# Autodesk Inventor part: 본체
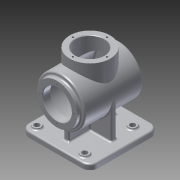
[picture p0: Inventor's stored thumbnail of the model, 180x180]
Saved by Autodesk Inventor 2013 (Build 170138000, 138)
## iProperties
Created: 2015-07
Part Number: 본체
Material: 알루미늄 6061
Document SubType Name: Modeling
Designer: Administrator
Density: 2.71 g/cm^3
Mass: 1276.78 g
Surface Area: 1269.7 cm^2
Volume: 471.138 cm^3
Author: Administrator
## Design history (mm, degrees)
sketch "스케치1"
  geometry: L1 (65, -65)-(-65, -65); L2 (-65, -65)-(-65, 65); L3 (-65, 65)-(65, 65); L4 (65, 65)-(65, -65); L5 (65, -65)-(-65, 65); L6 (-65, -65)-(65, 65); 1 further point
  constraints: 12 end point, 2 midpoint, 2 parallel, 1 horizontal, 1 perpendicular
  dimensions: "d0" = 130 distance of L2.end L3.end; "d2" = 130 distance of L1.end L2.end
extrude "돌출1" new body sketch "스케치1" distance "d3" = 10; taper "d4" = 0 deg
sketch "스케치2"
  geometry: L1 (-65, 0)-(-65, 10) reference; L2 (-65, 10)-(65, 10) reference; L3 (65, 10)-(65, 0) reference; L4 (65, 0)-(-65, 0) reference; L5 (-58.444, 78)-(85.766, 78); L6 (-62, 105)-(-62, 116); L7 (-62, 116)-(-58, 116); L8 (-55, 119)-(-55, 120); L9 (-52, 123)-(52, 123); L10 (55, 120)-(55, 78); L11 (48, 78)-(48, 115); L12 (45, 118)-(-45, 118); L13 (-48, 115)-(-48, 105); L14 (-48, 105)-(-62, 105); L15 (48, 78)-(55, 78); A1 r 3 centre (-52, 120) between (-52, 123) and (-55, 120); A2 r 3 centre (-58, 119) between (-58, 116) and (-55, 119); A3 r 3 centre (-45, 115) between (-45, 118) and (-48, 115); A4 r 3 centre (45, 115) between (48, 115) and (45, 118); A5 r 3 centre (52, 120) between (55, 120) and (52, 123); 3 further points
  constraints: 22 end point, 10 point on circle, 10 tangent, 6 parallel, 6 point on line, 5 centre point, 4 equal radius, 4 perpendicular, 1 collinear
  dimensions: "d5" = 78 distance from line of point (0, 0) L5; "d6" = 10 distance between parallel lines of L10 L3; "d7" = 90 diameter of L9 L5; "d8" = 80 diameter of L12 L5; "d9" = 54 diameter of L14 L5; "d10" = 76 diameter of L7 L5; "d11" = 14 distance of L13.end L6.start; "d12" = 96 distance of point (48, 118) point (-48, 118); "d13" = 7 distance between parallel lines of L10 L11; "d14" = 7 distance between parallel lines of L8 L6; "d15" = 3 radius of A1
revolve "회전1" sketch "스케치2" stored, may be unused: angle "d16" = 90 deg
fillet "모깎기1" dims "d17" = 15
node "작업 평면2"
sketch "스케치6"
  geometry: C1 r 38 at (0, 0); 1 further point
  constraints: 1 centre point, 1 coincident
  dimensions: "d20" = 76 diameter of C1
extrude "돌출2" join sketch "스케치6" stored distance "d21" = 10; taper "d22" = 0 deg
hole "구멍1" diameter "d25" = 54; stored, may be unused: countersink angle "d29" = 90 deg, drill point angle "d31" = 118 deg; dims "d23" = 10, "d24" = 10, "d26" = 6, "d27" = 4, "d28" = 2, "d30" = 8
chamfer "모따기1" distance "d32" = 1; stored, may be unused: second distance "d33" = 2, angle "d34" = 45 deg
sketch "스케치7"
  geometry: C1 r 38 at (0, 0) reference; 2 further points
  constraints: 1 vertical alignment
  dimensions: "d35" = 32 distance of point (0, 0) point (0, 32)
hole "구멍2" sketch "스케치7" at (0, 32) diameter "d36" = 3.242; stored, may be unused: countersink angle "d40" = 90 deg, drill point angle "d42" = 118 deg; dims "d37" = 8, "d38" = 4, "d39" = 2, "d41" = 10
sketch "스케치8"
  geometry: C1 r 38 at (0, 0) reference; 2 further points
  constraints: 1 vertical alignment
  dimensions: "d46" = 32 distance of C1.centre point (0, 32)
hole "구멍3" sketch "스케치8" at (0, 32) diameter "d47" = 3.242; stored, may be unused: countersink angle "d51" = 90 deg, drill point angle "d53" = 118 deg; dims "d48" = 8, "d49" = 4, "d50" = 2, "d52" = 10
sketch "스케치9"
  geometry: 1 further point
sketch "스케치10"
  geometry: L1 (-38, 102.104)-(-38, 140) reference; L2 (-38, 140)-(-33.621, 140) reference; L3 (-33.621, 140)-(-33.621, 130) reference; L4 (-33.621, 130)-(-32, 129.026) reference; L5 (-32, 129.026)-(-30.379, 130) reference; L6 (-30.379, 130)-(-30.379, 140) reference; L7 (-30.379, 140)-(-28, 140) reference; L8 (-28, 140)-(-27, 139) reference; L9 (-27, 139)-(-27, 107.513) reference; L10 (27, 107.513)-(27, 139) reference; L11 (27, 139)-(28, 140) reference; L12 (28, 140)-(30.379, 140) reference; L13 (30.379, 140)-(30.379, 130) reference; L14 (30.379, 130)-(32, 129.026) reference; L15 (32, 129.026)-(33.621, 130) reference; L16 (33.621, 130)-(33.621, 140) reference; L17 (33.621, 140)-(38, 140) reference; L18 (38, 140)-(38, 102.104) reference; L19 (65, 10)-(65, 0) reference; L20 (65, 0)-(-65, 0) reference; L21 (-65, 0)-(-65, 10) reference; L22 (-65, 10)-(65, 10) reference; L23 (45, 10)-(45, 78); L24 (-45, 10)-(-45, 78); A1 r 45 centre (0, 78) between (-38, 102.104) and (38, 102.104) reference; A2 r 40 centre (0, 78) between (-27, 107.513) and (27, 107.513) reference; 1 further point
  constraints: 4 end point, 2 point on circle, 2 point on line, 1 parallel, 1 perpendicular
  dimensions: "d57" = 90 distance between parallel lines of L24 L23; "d58" = 45 distance from line of L23 point (0, 0)
extrude "돌출3" join sketch "스케치10" stored distance "d59" = 10; taper "d60" = 0 deg
sketch "스케치11"
  geometry: L1 (-52, 123)-(-38, 123) reference; L2 (-38, 123)-(-38, 140) reference; L3 (-38, 140)-(-33.621, 140) reference; L4 (-33.621, 140)-(-33.621, 130) reference; L5 (-33.621, 130)-(-32, 129.026) reference; L6 (-32, 129.026)-(-30.379, 130) reference; L7 (-30.379, 130)-(-30.379, 140) reference; L8 (-30.379, 140)-(-28, 140) reference; L9 (-28, 140)-(-27, 139) reference; L10 (-27, 139)-(-27, 118) reference; L11 (-27, 118)-(-45, 118) reference; L12 (-48, 115)-(-48, 105) reference; L13 (-48, 105)-(-61, 105) reference; L14 (-61, 105)-(-62, 106) reference; L15 (-62, 106)-(-62, 108.379) reference; L16 (-62, 108.379)-(-52, 108.379) reference; L17 (-52, 108.379)-(-51.026, 110) reference; L18 (-51.026, 110)-(-52, 111.621) reference; L19 (-52, 111.621)-(-62, 111.621) reference; L20 (-62, 111.621)-(-62, 116) reference; L21 (-62, 116)-(-58, 116) reference; L22 (-55, 119)-(-55, 120) reference; L23 (48, 41)-(48, 115) reference; L24 (45, 118)-(27, 118) reference; L25 (27, 118)-(27, 139) reference; L26 (27, 139)-(28, 140) reference; L27 (28, 140)-(30.379, 140) reference; L28 (30.379, 140)-(30.379, 130) reference; L29 (30.379, 130)-(32, 129.026) reference; L30 (32, 129.026)-(33.621, 130) reference; L31 (33.621, 130)-(33.621, 140) reference; L32 (33.621, 140)-(38, 140) reference; L33 (38, 140)-(38, 123) reference; L34 (38, 123)-(52, 123) reference; L35 (55, 120)-(55, 36) reference; L36 (52, 33)-(5, 33) reference; L37 (5, 33)-(5, 10) reference; L38 (5, 10)-(65, 10) reference; L39 (65, 10)-(65, 0) reference; L40 (65, 0)-(-65, 0) reference; L41 (-65, 0)-(-65, 10) reference; L42 (-65, 10)-(-5, 10) reference; L43 (-5, 10)-(-5, 33) reference; L44 (-5, 33)-(-52, 33) reference; L45 (-55, 36)-(-55, 37) reference; L46 (-58, 40)-(-62, 40) reference; L47 (-62, 40)-(-62, 44.379) reference; L48 (-62, 44.379)-(-52, 44.379) reference; L49 (-52, 44.379)-(-51.026, 46) reference; L50 (-51.026, 46)-(-52, 47.621) reference; L51 (-52, 47.621)-(-62, 47.621) reference; L52 (-62, 47.621)-(-62, 50) reference; L53 (-62, 50)-(-61, 51) reference; L54 (-61, 51)-(-48, 51) reference; L55 (-48, 51)-(-48, 41) reference; L56 (-45, 38)-(45, 38) reference; L57 (-45, 33)-(-45, 10); L58 (45, 33)-(45, 10); A1 r 3 centre (-45, 115) between (-45, 118) and (-48, 115) reference; A2 r 3 centre (-58, 119) between (-58, 116) and (-55, 119) reference; A3 r 3 centre (-52, 120) between (-52, 123) and (-55, 120) reference; A4 r 3 centre (45, 115) between (48, 115) and (45, 118) reference; A5 r 3 centre (52, 120) between (55, 120) and (52, 123) reference; A6 r 3 centre (52, 36) between (52, 33) and (55, 36) reference; A7 r 3 centre (-52, 36) between (-55, 36) and (-52, 33) reference; A8 r 3 centre (-58, 37) between (-55, 37) and (-58, 40) reference; A9 r 3 centre (-45, 41) between (-48, 41) and (-45, 38) reference; A10 r 3 centre (45, 41) between (45, 38) and (48, 41) reference; 1 further point
  constraints: 4 end point, 4 point on line, 2 perpendicular
  dimensions: "d61" = 45 distance from line of L57 point (0, 0); "d62" = 45 distance from line of L58 point (0, 0)
  node "절단 모서리 투영3"
feature "리브1" dims "d63" = 1, "d64" = 10, "d65" = 0, "d66" = 0, "d67" = 1, "d68" = 1
feature "리브2" dims "d69" = 1, "d70" = 10, "d71" = 0, "d72" = 0, "d73" = 1, "d74" = 1
sketch "스케치12"
  geometry: C1 r 7.5 at (-50, -50); A1 r 15 centre (-50, -50) between (-65, -50) and (-50, -65) reference; 1 further point
  constraints: 1 centre point, 1 coincident
  dimensions: "d76" = 15 diameter of C1
extrude "돌출4" join sketch "스케치12" distance "d77" = 3; taper "d78" = 0 deg
hole "구멍4" diameter "d81" = 10; stored, may be unused: countersink angle "d85" = 90 deg, drill point angle "d87" = 118 deg; dims "d79" = 10, "d80" = 10, "d82" = 10, "d83" = 4, "d84" = 2, "d86" = 10
fillet "모깎기2" dims "d88" = 3
fillet "모깎기3" dims "d95" = 3
fillet "모깎기4" dims "d96" = 3
sketch "스케치13"
  geometry: C1 r 45 at (0, 0) reference; C2 r 40 at (0, 0) reference; 2 further points
  constraints: 1 coincident, 1 other
feature "엠보싱1" sketch "스케치13" dims "d0" = 130, "d2" = 130, "d5" = 78, "d6" = 10, "d7" = 90, "d8" = 80, "d9" = 54, "d10" = 76, "d11" = 14, "d12" = 96, "d13" = 7, "d14" = 7, "d15" = 3, "d97" = 0.5, "d98" = 0
fillet "모깎기5" dims "d101" = 2
node "솔리드1"
pattern_circular "원형 패턴1" dims angle "d44" = 360 deg
pattern_circular "원형 패턴2" dims angle "d55" = 360 deg
pattern_linear "직사각형 패턴1"
node "절단 모서리 투영1"
node "절단 모서리 투영2"
